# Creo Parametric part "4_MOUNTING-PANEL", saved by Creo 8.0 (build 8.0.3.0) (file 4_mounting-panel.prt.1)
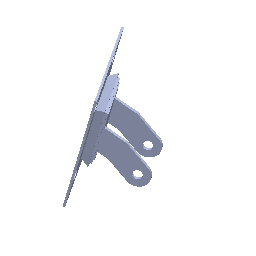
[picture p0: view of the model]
Units: millimeter Newton Second (mmNs); MM, TONNE, SECS

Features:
  1. protrusion
  2. datum plane "DTM1"
  3. cut
  4. datum plane "DTM2"
  5. datum plane "DTM3"
  6. protrusion
  7. protrusion
  8. protrusion
  9. datum plane "DTM4"
  10. protrusion
  11. cut
  12. protrusion
  13. cut
  14. round

Other named items: COPIED_GROUP

Layers: 0_ALL_AXIS, 0_ALL_CSYS, 0_ALL_CURVES, 0_ALL_PLANES, 0_ALL_POINTS, 0_ALL_SURFS, MOUNTING-PANEL

Surfaces: 33 plane, 13 cylinder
